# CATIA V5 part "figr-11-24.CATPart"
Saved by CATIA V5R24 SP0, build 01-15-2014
Part number: Part1
Bounding box of the stored display mesh (mm): x -89.703 to 75.958, y -127.286 to 108.862, z -26.487 to 19.815
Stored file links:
  D:\KAVITA\CATIA V5-6R2014 Project_ Kavita\CATIA V5-6R2014_partfiles\Partfiles\c11_catia_v5-6r2014_prt\figr-11-24.CATPart
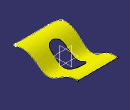
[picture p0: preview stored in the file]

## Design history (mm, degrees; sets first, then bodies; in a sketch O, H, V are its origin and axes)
Set1
  Extrude1: Element1 Sketch3, Lim1 86, Lim2 94, Direction yz-plane
  Sketch1 on xy-plane, origin (0, 0, 0), H (1, 0, 0), V (0, 1, 0)
    line L1 (64.3059, 108.8616) -> (75.9293, -106.0218)
    arc A1 centre (55.7837, -107.1115) radius 20.175 from (75.9293, -106.0218) to (55.7837, -127.2865) cw
    line L2 (55.7837, -127.2865) -> (-64.7868, -127.2865)
    arc A2 centre (-64.7868, -102.3613) radius 24.9252 from (-64.7868, -127.2865) to (-89.6873, -101.2501) cw
    line L3 (-89.6873, -101.2501) -> (-80.3115, 108.8616)
    line L4 (-80.3115, 108.8616) -> (64.3059, 108.8616)
    tangency: A1 L1, A2 L2, A2 L3, A1 L2
    horizontal: L2 H, L4 H
  Extrude2: Element1 Sketch1, Lim1 86, Lim2 94, Direction xy-plane
  Split1: ToCut Extrude1, Cutting Extrude2
  Sketch2 on xy-plane, origin (0, 0, 0), H (1, 0, 0), V (0, 1, 0)
    construction line L1 (-11.3849, 28.4134) -> (-11.3849, -36.9379)
    line L2 (12.8382, 28.4134) -> (12.8382, -36.9379)
    line L3 (-35.608, -36.9379) -> (-35.608, 28.4134)
    arc A1 centre (-11.3849, -36.9379) radius 24.2231 from (12.8382, -36.9379) to (-35.608, -36.9379) cw
    arc A2 centre (-11.3849, 28.4134) radius 24.2231 from (-35.608, 28.4134) to (12.8382, 28.4134) cw
    vertical: L1 V
    tangency: A1 L2, A2 L2, A1 L3, A2 L3
    parallelism: L1 L2
  Extrude3: Element1 Sketch2, Lim1 86, Lim2 94, Direction xy-plane
  Split2: ToCut Split1, Cutting Extrude3
  Boundary1: Boundary edge of Split2, Support Split2
Body1 (main body)
  Sketch3 on yz-plane, origin (0, 0, 0), H (0, 1, 0), V (0, 0, 1)
    spline S1 through (-130.9721, 0) (-85.5087, 19.8151) (-38.0512, 0) (0, -25.6483) (60.0541, -1.7202) (134.7951, -4.3868)
    point P1 (-130.9721, 0)
    point P2 (-38.0512, 0)
    point P3 (0, -25.6483)
    coincidence: P1 H, P2 H, P3 V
